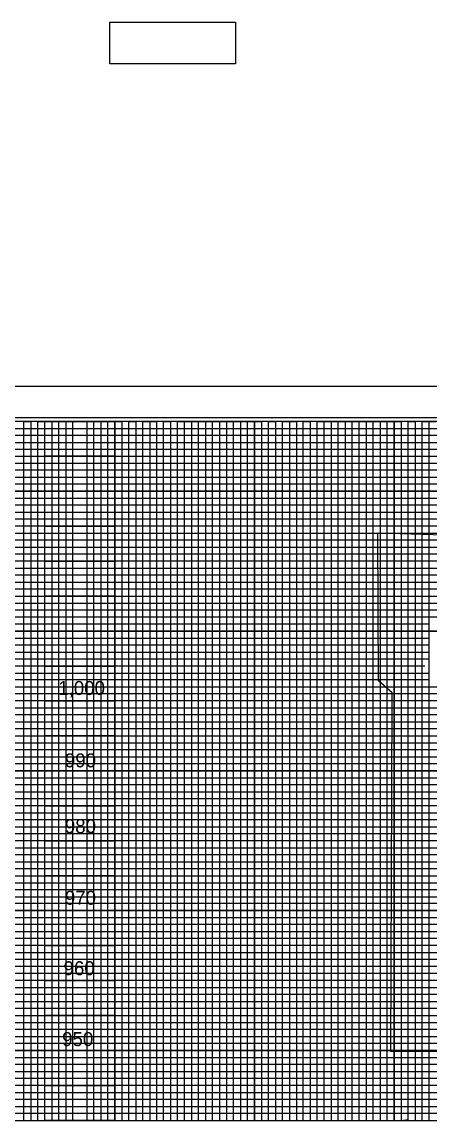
# Model space of a CAD drawing. Extents: x 1628636 to 1631253, y 896159 to 897520.
# Drawn here: x 1629810 to 1630102, y 896731 to 897520 of the extents above; entities that cross this region are included whole.
import ezdxf

# ---------------------------------------------------------------- set-up
doc = ezdxf.new("R2010")
doc.units = 0
for name, color, linetype in [('Prop DSN Text', 7, 'Continuous'), ('Prop PHM Black Shape', 7, 'Continuous'), ('Scratch_Level_6', 7, 'Continuous'), ('Sheet Cutting Line CELL', 7, 'Continuous'), ('Sheet DOT Grid CELL', 7, 'Continuous'), ('Sheet Layout Profile Border Port 1', 7, 'Continuous'), ('Sheet Plot Border Inside CELL', 7, 'Continuous'), ('Sheet Plot Border Outside CELL', 7, 'Continuous'), ('Sheet Profile CELL', 7, 'Continuous'), ('Sheet Profile Grid Major CELL', 7, 'Continuous'), ('Sheet Profile Grid Middle CELL', 7, 'Continuous'), ('Sheet Profile Grid Minor CELL', 7, 'Continuous')]:
    doc.layers.add(name, color=color, linetype=linetype)

msp = doc.modelspace()

# ---------------------------------------------------------------- linework, layer by layer
at = {"layer": 'Prop PHM Black Shape'}
for points in [[(1629872.87, 897519.57), (1629962.87, 897519.57), (1629962.87, 897489.57), (1629872.87, 897489.57)], [(1629826.5, 897233.9), (1629876.5, 897233.9), (1629876.5, 897208.9), (1629826.5, 897208.9)], [(1629826.5, 897208.9), (1629876.5, 897208.9), (1629876.5, 897183.9), (1629826.5, 897183.9)], [(1629826.5, 897183.9), (1629876.5, 897183.9), (1629876.5, 897158.9), (1629826.5, 897158.9)], [(1629826.5, 897158.9), (1629876.5, 897158.9), (1629876.5, 897133.9), (1629826.5, 897133.9)], [(1629826.5, 897133.9), (1629876.5, 897133.9), (1629876.5, 897108.9), (1629826.5, 897108.9)], [(1629826.5, 897108.9), (1629876.5, 897108.9), (1629876.5, 897083.9), (1629826.5, 897083.9)], [(1629826.5, 897083.9), (1629876.5, 897083.9), (1629876.5, 897058.9), (1629826.5, 897058.9)], [(1629826.5, 897058.9), (1629876.5, 897058.9), (1629876.5, 897033.9), (1629826.5, 897033.9)], [(1629826.5, 897033.9), (1629876.5, 897033.9), (1629876.5, 897008.9), (1629826.5, 897008.9)], [(1629826.5, 897008.9), (1629876.5, 897008.9), (1629876.5, 896983.9), (1629826.5, 896983.9)], [(1629826.5, 896983.9), (1629876.5, 896983.9), (1629876.5, 896958.9), (1629826.5, 896958.9)], [(1629826.5, 896958.9), (1629876.5, 896958.9), (1629876.5, 896933.9), (1629826.5, 896933.9)], [(1629826.5, 896933.9), (1629876.5, 896933.9), (1629876.5, 896908.9), (1629826.5, 896908.9)], [(1629826.5, 896908.9), (1629876.5, 896908.9), (1629876.5, 896883.9), (1629826.5, 896883.9)], [(1629826.5, 896883.9), (1629876.5, 896883.9), (1629876.5, 896858.9), (1629826.5, 896858.9)], [(1629826.5, 896858.9), (1629876.5, 896858.9), (1629876.5, 896833.9), (1629826.5, 896833.9)], [(1629826.5, 896833.9), (1629876.5, 896833.9), (1629876.5, 896808.9), (1629826.5, 896808.9)], [(1629826.5, 896808.9), (1629876.5, 896808.9), (1629876.5, 896783.9), (1629826.5, 896783.9)], [(1629826.5, 896783.9), (1629876.5, 896783.9), (1629876.5, 896758.9), (1629826.5, 896758.9)], [(1629826.5, 896758.9), (1629876.5, 896758.9), (1629876.5, 896733.9), (1629826.5, 896733.9)]]:
    msp.add_lwpolyline(points, close=True, dxfattribs=at)
at = {"layer": 'Scratch_Level_6'}
for points in [[(1629976.5, 897183.9), (1630476.5, 897183.9), (1630476.5, 896758.9), (1629976.5, 896758.9)], [(1630074.97, 896969.15), (1630075.03, 897039.83), (1630065.35, 897048.31), (1630064.94, 897154.26), (1630493.96, 897141.36), (1630495.42, 896780.43), (1630074.26, 896783.19)]]:
    msp.add_lwpolyline(points, close=True, dxfattribs=at)
at = {"layer": 'Sheet Cutting Line CELL'}
msp.add_line((1630743.5, 897258.9), (1629059.5, 897258.9), dxfattribs=at)
at = {"layer": 'Sheet DOT Grid CELL'}
for p, q in [((1629826.5, 896733.9), (1629826.5, 897233.9)), ((1629876.5, 896733.9), (1629876.5, 897233.9)), ((1629926.5, 896733.9), (1629926.5, 897233.9)), ((1629976.5, 896733.9), (1629976.5, 897233.9)), ((1630026.5, 896733.9), (1630026.5, 897233.9)), ((1630076.5, 896733.9), (1630076.5, 897233.9)), ((1630526.45, 897183.9), (1629226.5, 897183.9)), ((1630526.45, 897133.9), (1629226.5, 897133.9)), ((1630526.5, 897083.9), (1629226.5, 897083.9)), ((1630726.5, 897033.9), (1629226.5, 897033.9)), ((1630726.5, 896983.9), (1629226.5, 896983.9)), ((1630726.5, 896933.9), (1629226.5, 896933.9)), ((1630726.5, 896883.9), (1629226.5, 896883.9)), ((1630726.5, 896833.9), (1629226.5, 896833.9)), ((1630726.5, 896783.9), (1629226.5, 896783.9))]:
    msp.add_line(p, q, dxfattribs=at)
at = {"layer": 'Sheet Layout Profile Border Port 1'}
msp.add_lwpolyline([(1629276.5, 897072.85), (1629276.5, 896733.9), (1630676.5, 896733.9), (1630676.5, 897072.85)], dxfattribs=at)
at = {"layer": 'Sheet Plot Border Inside CELL'}
msp.add_lwpolyline([(1629072.5, 896181.35), (1630739, 896181.35), (1630739, 897236.45), (1629072.5, 897236.45)], close=True, dxfattribs=at)
at = {"layer": 'Sheet Plot Border Outside CELL'}
msp.add_lwpolyline([(1629059.5, 896158.9), (1630743.5, 896158.9), (1630743.5, 897258.9), (1629059.5, 897258.9)], close=True, dxfattribs=at)
at = {"layer": 'Sheet Profile CELL'}
msp.add_line((1629226.5, 896733.9), (1630726.5, 896733.9), dxfattribs=at)
msp.add_lwpolyline([(1630726.5, 897233.9), (1629226.5, 897233.9), (1629226.5, 896183.9), (1630726.5, 896183.9)], close=True, dxfattribs=at)
at = {"layer": 'Sheet Profile Grid Major CELL'}
for p, q in [((1629826.5, 897208.9), (1629876.5, 897208.9)), ((1629826.5, 897183.9), (1629876.5, 897183.9)), ((1629826.5, 897158.9), (1629876.5, 897158.9)), ((1629826.5, 897133.9), (1629876.5, 897133.9)), ((1629826.5, 897108.9), (1629876.5, 897108.9)), ((1629826.5, 897083.9), (1629876.5, 897083.9)), ((1629826.5, 897058.9), (1629876.5, 897058.9)), ((1629826.5, 897033.9), (1629876.5, 897033.9)), ((1629826.5, 897008.9), (1629876.5, 897008.9)), ((1629826.5, 896983.9), (1629876.5, 896983.9)), ((1629826.5, 896958.9), (1629876.5, 896958.9)), ((1629826.5, 896933.9), (1629876.5, 896933.9)), ((1629826.5, 896908.9), (1629876.5, 896908.9)), ((1629826.5, 896883.9), (1629876.5, 896883.9)), ((1629826.5, 896858.9), (1629876.5, 896858.9)), ((1629826.5, 896833.9), (1629876.5, 896833.9)), ((1629826.5, 896808.9), (1629876.5, 896808.9)), ((1629826.5, 896783.9), (1629876.5, 896783.9)), ((1629826.5, 896758.9), (1629876.5, 896758.9))]:
    msp.add_line(p, q, dxfattribs=at)
for points in [[(1629776.5, 896733.9), (1629826.5, 896733.9), (1629826.5, 897233.9), (1629876.5, 897233.9), (1629876.5, 896733.9), (1629926.5, 896733.9), (1629926.5, 897233.9), (1629976.5, 897233.9), (1629976.5, 896733.9), (1630026.5, 896733.9), (1630026.5, 897233.9), (1630076.5, 897233.9), (1630076.5, 896733.9), (1630126.5, 896733.9)], [(1629226.5, 897183.9), (1630526.5, 897183.9)], [(1630526.5, 897133.9), (1629226.5, 897133.9), (1629226.5, 897083.9), (1630526.5, 897083.9)], [(1630726.5, 897033.9), (1629226.5, 897033.9), (1629226.5, 896983.9), (1630726.5, 896983.9)], [(1630726.5, 896933.9), (1629226.5, 896933.9), (1629226.5, 896883.9), (1630726.5, 896883.9)], [(1630726.5, 896833.9), (1629226.5, 896833.9), (1629226.5, 896833.9), (1629226.5, 896783.9), (1630726.5, 896783.9)]]:
    msp.add_lwpolyline(points, dxfattribs=at)
at = {"layer": 'Sheet Profile Grid Middle CELL'}
msp.add_line((1629226.5, 897208.9), (1630526.45, 897208.9), dxfattribs=at)
for points in [[(1630526.5, 897158.9), (1629226.5, 897158.9), (1629226.5, 897108.9), (1630526.5, 897108.9)], [(1630098.37, 897058.9), (1629226.5, 897058.9), (1629226.5, 897008.9), (1630551.5, 897008.9)], [(1630726.5, 896958.9), (1629226.5, 896958.9), (1629226.5, 896908.9), (1630726.5, 896908.9)], [(1630726.5, 896858.9), (1629226.5, 896858.9), (1629226.5, 896808.9), (1630726.5, 896808.9)], [(1630726.5, 896758.9), (1629226.5, 896758.9)]]:
    msp.add_lwpolyline(points, dxfattribs=at)
at = {"layer": 'Sheet Profile Grid Minor CELL'}
for p, q in [((1629811.5, 896733.9), (1629811.5, 897233.9)), ((1629811.5, 897233.9), (1629816.5, 897233.9)), ((1629816.5, 897233.9), (1629816.5, 896733.9)), ((1629821.5, 896733.9), (1629821.5, 897233.9)), ((1629821.5, 897233.9), (1629831.5, 897233.9)), ((1629831.5, 897233.9), (1629831.5, 896733.9)), ((1629836.5, 896733.9), (1629836.5, 897233.9)), ((1629836.5, 897233.9), (1629841.5, 897233.9)), ((1629841.5, 897233.9), (1629841.5, 896733.9)), ((1629846.5, 896733.9), (1629846.5, 897233.9)), ((1629846.5, 897233.9), (1629856.5, 897233.9)), ((1629856.5, 897233.9), (1629856.5, 896733.9)), ((1629861.5, 896733.9), (1629861.5, 897233.9)), ((1629861.5, 897233.9), (1629866.5, 897233.9)), ((1629866.5, 897233.9), (1629866.5, 896733.9)), ((1629871.5, 896733.9), (1629871.5, 897233.9)), ((1629871.5, 897233.9), (1629881.5, 897233.9)), ((1629881.5, 897233.9), (1629881.5, 896733.9)), ((1629886.5, 896733.9), (1629886.5, 897233.9)), ((1629886.5, 897233.9), (1629891.5, 897233.9)), ((1629891.5, 897233.9), (1629891.5, 896733.9)), ((1629896.5, 896733.9), (1629896.5, 897233.9)), ((1629896.5, 897233.9), (1629906.5, 897233.9)), ((1629901.5, 897233.9), (1629901.5, 896733.9)), ((1629906.5, 897233.9), (1629906.5, 896733.9)), ((1629911.5, 896733.9), (1629911.5, 897233.9)), ((1629911.5, 897233.9), (1629916.5, 897233.9)), ((1629916.5, 897233.9), (1629916.5, 896733.9)), ((1629921.5, 896733.9), (1629921.5, 897233.9)), ((1629921.5, 897233.9), (1629931.5, 897233.9)), ((1629931.5, 897233.9), (1629931.5, 896733.9)), ((1629936.5, 896733.9), (1629936.5, 897233.9)), ((1629936.5, 897233.9), (1629941.5, 897233.9)), ((1629941.5, 897233.9), (1629941.5, 896733.9)), ((1629946.5, 896733.9), (1629946.5, 897233.9)), ((1629946.5, 897233.9), (1629956.5, 897233.9)), ((1629951.5, 897233.9), (1629951.5, 896733.9)), ((1629956.5, 897233.9), (1629956.5, 896733.9)), ((1629961.5, 896733.9), (1629961.5, 897233.9)), ((1629961.5, 897233.9), (1629966.5, 897233.9)), ((1629966.5, 897233.9), (1629966.5, 896733.9)), ((1629971.5, 896733.9), (1629971.5, 897233.9)), ((1629971.5, 897233.9), (1629981.5, 897233.9)), ((1629981.5, 897233.9), (1629981.5, 896733.9)), ((1629986.5, 896733.9), (1629986.5, 897233.9)), ((1629986.5, 897233.9), (1629991.5, 897233.9)), ((1629991.5, 897233.9), (1629991.5, 896733.9)), ((1629996.5, 896733.9), (1629996.5, 897233.9)), ((1629996.5, 897233.9), (1630006.5, 897233.9)), ((1630001.5, 897233.9), (1630001.5, 896733.9)), ((1630006.5, 897233.9), (1630006.5, 896733.9)), ((1630011.5, 896733.9), (1630011.5, 897233.9)), ((1630011.5, 897233.9), (1630016.5, 897233.9)), ((1630016.5, 897233.9), (1630016.5, 896733.9)), ((1630021.5, 896733.9), (1630021.5, 897233.9)), ((1630021.5, 897233.9), (1630031.5, 897233.9)), ((1630031.5, 897233.9), (1630031.5, 896733.9)), ((1630036.5, 896733.9), (1630036.5, 897233.9)), ((1630036.5, 897233.9), (1630041.5, 897233.9)), ((1630041.5, 897233.9), (1630041.5, 896733.9)), ((1630046.5, 896733.9), (1630046.5, 897233.9)), ((1630046.5, 897233.9), (1630056.5, 897233.9)), ((1630051.5, 896733.9), (1630051.5, 897233.9)), ((1630056.5, 897233.9), (1630056.5, 896733.9)), ((1630061.5, 896733.9), (1630061.5, 897233.9)), ((1630061.5, 897233.9), (1630066.5, 897233.9)), ((1630066.5, 897233.9), (1630066.5, 896733.9)), ((1630071.5, 896733.9), (1630071.5, 897233.9)), ((1630071.5, 897233.9), (1630081.5, 897233.9)), ((1630081.5, 897233.9), (1630081.5, 896733.9)), ((1630086.5, 896733.9), (1630086.5, 897233.9)), ((1630086.5, 897233.9), (1630091.5, 897233.9)), ((1630091.5, 897233.9), (1630091.5, 896733.9)), ((1630096.5, 896733.9), (1630096.5, 897233.9)), ((1630096.5, 897233.9), (1630106.5, 897233.9)), ((1630101.43, 897233.9), (1630101.43, 896733.9)), ((1629276.5, 897228.9), (1630526.5, 897228.9)), ((1630526.5, 897223.9), (1629276.5, 897223.55)), ((1629276.5, 897218.9), (1630526.5, 897218.9)), ((1630526.45, 897098.9), (1629276.5, 897098.9)), ((1630526.5, 897093.9), (1629276.5, 897093.9)), ((1630101.43, 897088.9), (1629276.5, 897088.9)), ((1629276.5, 897078.9), (1630101.43, 897078.9)), ((1630101.43, 897073.9), (1629276.5, 897073.9)), ((1629276.5, 897068.9), (1630101.5, 897068.9)), ((1630101.43, 897048.9), (1629276.5, 897048.9)), ((1629276.5, 897043.9), (1630171.5, 897043.9)), ((1630676.5, 897023.9), (1629276.5, 897023.9)), ((1629276.5, 897018.9), (1630676.5, 897018.9)), ((1630676.5, 896998.9), (1629276.5, 896998.9)), ((1629276.5, 896993.9), (1630676.5, 896993.9)), ((1630676.5, 896988.9), (1629276.5, 896988.9)), ((1629276.5, 896978.9), (1630676.5, 896978.9)), ((1630676.5, 896973.9), (1629276.5, 896973.9)), ((1629276.5, 896968.9), (1630676.5, 896968.9)), ((1630676.5, 896963.9), (1629276.5, 896963.9)), ((1629276.5, 896953.9), (1630676.5, 896953.9)), ((1630676.5, 896948.9), (1629276.5, 896948.9)), ((1629276.5, 896943.9), (1630676.5, 896943.9)), ((1630676.5, 896938.9), (1629276.5, 896938.9)), ((1629276.5, 896928.9), (1630676.5, 896928.9)), ((1630676.5, 896923.9), (1629276.5, 896923.9)), ((1629276.5, 896918.9), (1630676.5, 896918.9)), ((1630676.5, 896913.9), (1629276.5, 896913.9)), ((1629276.5, 896903.9), (1630676.5, 896903.9)), ((1630676.5, 896898.9), (1629276.5, 896898.9)), ((1629276.5, 896893.9), (1630676.5, 896893.9)), ((1630676.5, 896888.9), (1629276.5, 896888.9)), ((1629276.5, 896878.9), (1630676.5, 896878.9)), ((1630676.5, 896873.9), (1629276.5, 896873.9)), ((1629276.5, 896868.9), (1630676.5, 896868.9)), ((1630676.5, 896863.9), (1629276.5, 896863.9)), ((1629276.5, 896853.9), (1630676.5, 896853.9)), ((1630676.5, 896848.9), (1629276.5, 896848.9)), ((1630676.5, 896843.9), (1629276.5, 896843.9)), ((1630676.5, 896838.9), (1629276.5, 896838.9)), ((1629276.5, 896828.9), (1630676.5, 896828.9)), ((1630676.5, 896823.9), (1629276.5, 896823.9)), ((1629276.5, 896818.9), (1630676.5, 896818.9)), ((1630676.5, 896813.9), (1629276.5, 896813.9)), ((1629276.5, 896803.9), (1630676.5, 896803.9)), ((1630676.5, 896798.9), (1629276.5, 896798.9)), ((1629276.5, 896793.9), (1630676.5, 896793.9)), ((1630676.5, 896788.9), (1629276.5, 896788.9)), ((1629276.5, 896778.9), (1630676.5, 896778.9)), ((1630676.5, 896773.9), (1629276.5, 896773.9)), ((1629276.5, 896768.9), (1630676.5, 896768.9)), ((1630676.5, 896763.9), (1629276.5, 896763.9)), ((1629276.5, 896753.9), (1630676.5, 896753.9)), ((1630676.5, 896748.9), (1629276.5, 896748.9)), ((1629276.5, 896743.9), (1630676.5, 896743.9)), ((1629806.5, 896733.9), (1629811.5, 896733.9)), ((1629816.5, 896733.9), (1629821.5, 896733.9)), ((1629831.5, 896733.9), (1629836.5, 896733.9)), ((1629841.5, 896733.9), (1629846.5, 896733.9)), ((1629856.5, 896733.9), (1629861.5, 896733.9)), ((1629866.5, 896733.9), (1629871.5, 896733.9)), ((1629881.5, 896733.9), (1629886.5, 896733.9)), ((1629891.5, 896733.9), (1629896.5, 896733.9)), ((1629906.5, 896733.9), (1629911.5, 896733.9)), ((1629916.5, 896733.9), (1629921.5, 896733.9)), ((1629931.5, 896733.9), (1629931.5, 896733.9)), ((1629931.5, 896733.9), (1629936.5, 896733.9)), ((1629941.5, 896733.9), (1629946.5, 896733.9)), ((1629956.5, 896733.9), (1629961.5, 896733.9)), ((1629966.5, 896733.9), (1629971.5, 896733.9)), ((1629981.5, 896733.9), (1629986.5, 896733.9)), ((1629991.5, 896733.9), (1629996.5, 896733.9)), ((1630006.5, 896733.9), (1630011.5, 896733.9)), ((1630016.5, 896733.9), (1630021.5, 896733.9)), ((1630031.5, 896733.9), (1630036.5, 896733.9)), ((1630041.5, 896733.9), (1630046.5, 896733.9)), ((1630056.5, 896733.9), (1630061.5, 896733.9)), ((1630066.5, 896733.9), (1630071.5, 896733.9)), ((1630081.5, 896733.9), (1630086.2, 896734.45)), ((1630086.2, 896734.45), (1630086.5, 896733.9)), ((1630091.5, 896733.9), (1630096.5, 896733.9))]:
    msp.add_line(p, q, dxfattribs=at)
for points in [[(1630526.5, 897213.9), (1629276.5, 897213.9), (1629276.5, 897203.9), (1630526.5, 897203.9)], [(1630526.45, 897198.9), (1629276.5, 897198.9), (1629276.5, 897193.9), (1630526.5, 897193.9)], [(1630526.5, 897188.9), (1629276.5, 897188.9), (1629276.5, 897178.9), (1630526.5, 897178.9)], [(1630526.5, 897173.9), (1629276.5, 897173.9), (1629276.5, 897168.9), (1630526.5, 897168.9)], [(1630526.5, 897163.9), (1629276.5, 897163.9), (1629276.5, 897153.9), (1630526.5, 897153.9)], [(1630526.5, 897148.9), (1629276.5, 897148.9), (1629276.5, 897143.9), (1630526.5, 897143.9)], [(1630526.5, 897138.9), (1629276.5, 897138.9), (1629276.5, 897128.9), (1630526.5, 897128.9)], [(1630526.5, 897123.8), (1629276.6, 897123.8), (1629276.6, 897118.9), (1630526.5, 897118.9)], [(1630526.5, 897113.9), (1629276.5, 897113.9), (1629276.5, 897103.9), (1630526.5, 897103.9)], [(1630101.43, 897063.9), (1629276.5, 897063.9), (1629276.5, 897053.9), (1630101.43, 897053.9)], [(1630676.5, 897038.9), (1629276.5, 897038.9), (1629276.5, 897028.9), (1630676.5, 897028.9)], [(1630676.5, 897013.9), (1629276.5, 897013.9), (1629276.5, 897003.9), (1630676.5, 897003.9)], [(1630676.5, 896738.9), (1629276.5, 896738.9)]]:
    msp.add_lwpolyline(points, dxfattribs=at)

# ---------------------------------------------------------------- texts
at = {"layer": 'Prop DSN Text'}
for s, p in [('1,000', (1629836.05, 897038.17)), ('990', (1629840.79, 896986.41)), ('980', (1629840.79, 896939.33)), ('970', (1629840.79, 896888.14)), ('960', (1629839.87, 896837.72)), ('950', (1629838.83, 896787.05))]:
    msp.add_text(s, height=10, dxfattribs=at).set_placement(p)

doc.saveas('drawing.dxf')
